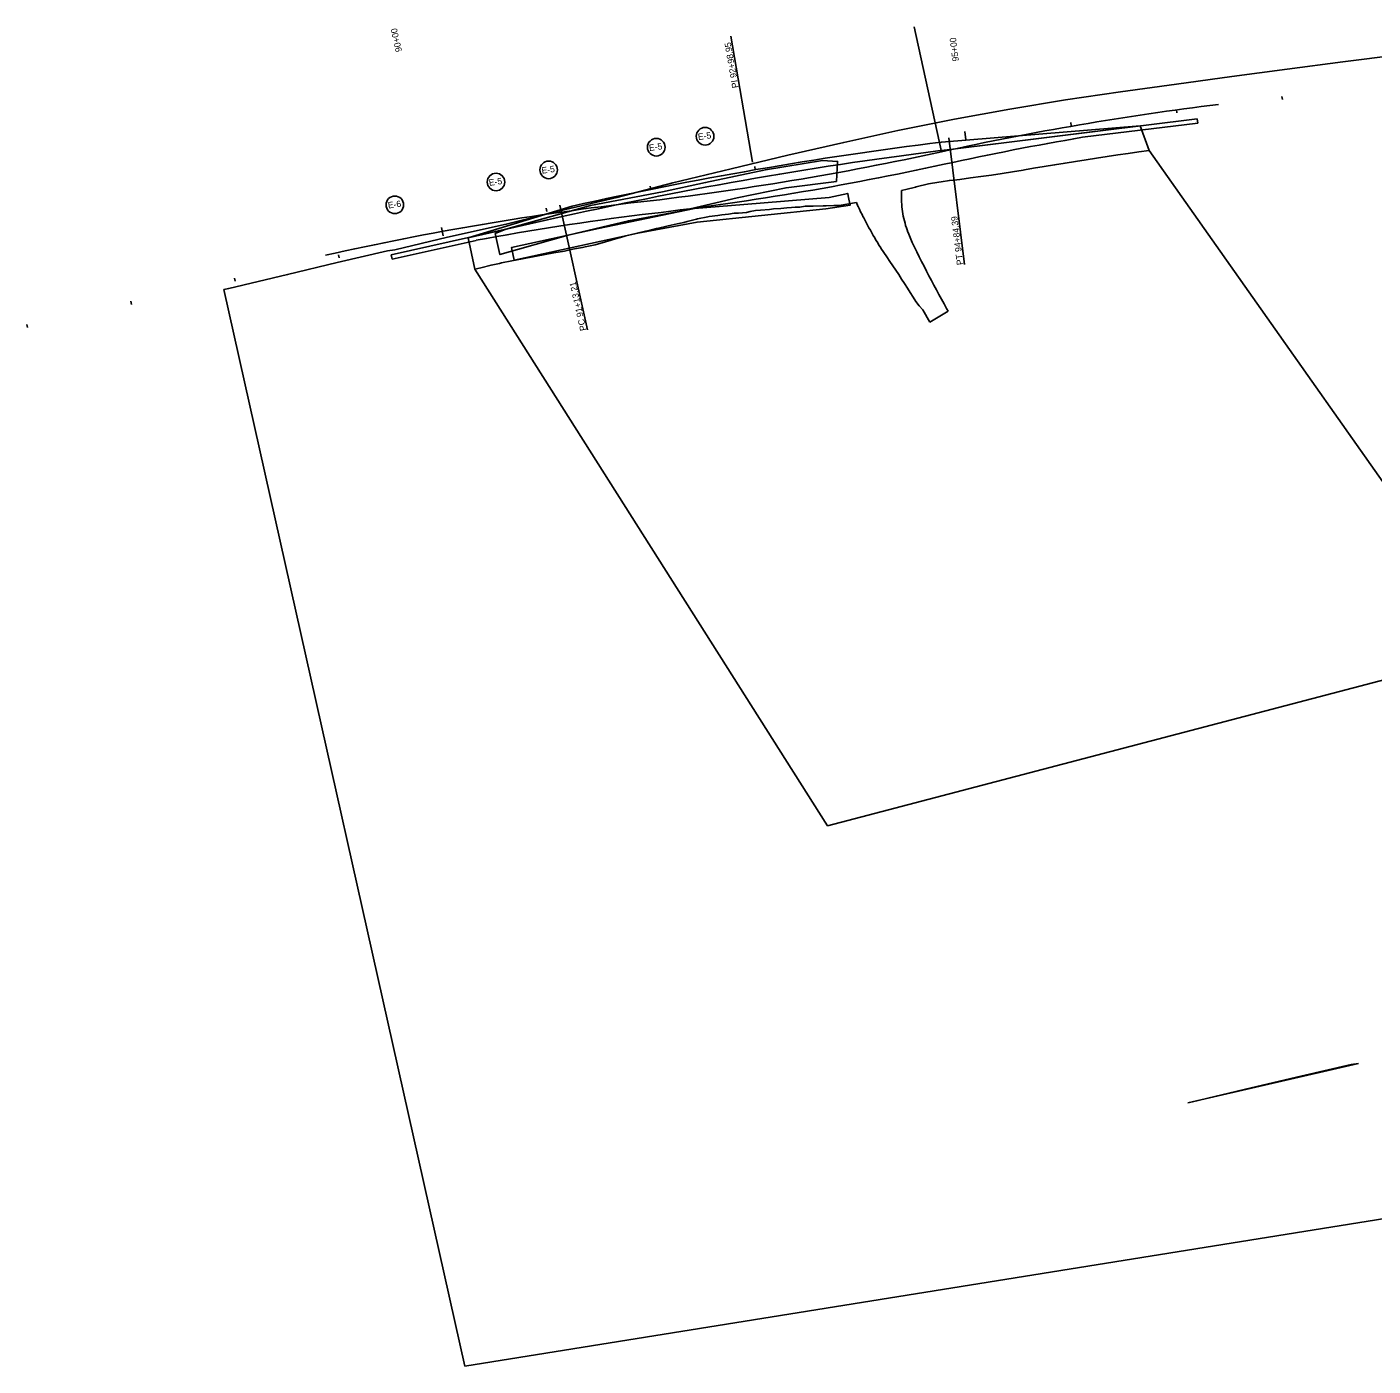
# Model space of a CAD drawing. Extents: x 1568908 to 1572777, y 730965 to 733090.
# Drawn here: x 1568908 to 1570174, y 730965 to 732223 of the extents above; entities that cross this region are included whole.
import ezdxf

# ---------------------------------------------------------------- set-up
doc = ezdxf.new("R2010")
doc.units = 0
for name, color, linetype in [('R_Erosion', 7, 'Continuous'), ('R_Horz Alg', 7, 'Continuous'), ('R_Horz Alg Annot', 7, 'Continuous'), ('R_No Plot', 7, 'Continuous')]:
    doc.layers.add(name, color=color, linetype=linetype)

msp = doc.modelspace()

# ---------------------------------------------------------------- linework, layer by layer
at = {"layer": 'R_Erosion'}
for centre in [(1569545.7, 732120.4), (1569499.8, 732110.1), (1569349.2, 732077.4), (1569398.7, 732088.8), (1569254.1, 732056)]:
    msp.add_circle(centre, 8.26, dxfattribs=at)
at = {"layer": 'R_Horz Alg'}
for centre, start, end in [((1570380, 729307.2), 97.05, 102.3359), ((1569155.9, 734904.5), 276.6023, 282.3359), ((1569814.7, 729213), 96.6023, 102.6177)]:
    msp.add_arc(centre, 2864.8, start, end, dxfattribs=at)
at = {"layer": 'R_Horz Alg Annot'}
for points in [[(1569590.4, 732096.2), (1569569.9, 732214.4)], [(1569767.9, 732105.9), (1569742.3, 732223.1)], [(1570088.3, 732154.8), (1570087.9, 732157.7)], [(1569989, 732142.5), (1569988.7, 732145.5)], [(1569789.7, 732124.9), (1569790.7, 732117)], [(1569889.8, 732130.2), (1569889.4, 732133.2)], [(1569774.7, 732119), (1569789.4, 731999.9)], [(1569592.8, 732089), (1569592.3, 732092)], [(1569494.6, 732070.7), (1569494, 732073.6)], [(1569396.9, 732049.8), (1569396.2, 732052.8)], [(1569409.1, 732055.6), (1569435.3, 731938.5)], [(1569297.8, 732034.8), (1569299.5, 732027)], [(1569201.7, 732006.1), (1569201, 732009.1)], [(1569104.1, 731984.3), (1569103.5, 731987.2)], [(1569006.5, 731962.4), (1569005.9, 731965.4)], [(1568908.9, 731940.6), (1568908.3, 731943.5)]]:
    msp.add_lwpolyline(points, dxfattribs=at)
at = {"layer": 'R_No Plot'}
for p, q in [((1570008.2, 732136.8), (1569776, 732108.1)), ((1570008.7, 732132.8), (1570008.2, 732136.8)), ((1569954.7, 732130.2), (1569767.8, 732114.9)), ((1569954.7, 732130.2), (1569776, 732108.1)), ((1569900.4, 732119.4), (1570008.7, 732132.8)), ((1569963.2, 732107), (1569954.7, 732130.2)), ((1569420.8, 732054.8), (1569323.1, 732025.1)), ((1569411.5, 732044.9), (1569250.7, 732008.9)), ((1569411.5, 732044.9), (1569323.1, 732025.1)), ((1569486.7, 732046.8), (1569486.7, 732046.8)), ((1569251.6, 732005), (1569330.4, 732022.6)), ((1569323.1, 732025.1), (1569329.4, 731995.6)), ((1569247.2, 732012.7), (1569247.1, 732012.7)), ((1569247.2, 732012.7), (1569247.1, 732012.7)), ((1569247.2, 732012.7), (1569247.1, 732012.7)), ((1569247.2, 732012.7), (1569247.1, 732012.7)), ((1569254.2, 732013.6), (1569247.2, 732012.7)), ((1569254.2, 732013.6), (1569247.2, 732012.7)), ((1569254.2, 732013.6), (1569247.2, 732012.7)), ((1569254.2, 732013.6), (1569247.2, 732012.7)), ((1569250.7, 732008.9), (1569251.6, 732005)), ((1569093.5, 731976.4), (1569320, 730964.9)), ((1569093.5, 731976.4), (1569320, 730964.9)), ((1569093.5, 731976.4), (1569320, 730964.9)), ((1569093.5, 731976.4), (1569320, 730964.9)), ((1569774.2, 731956), (1569772.7, 731958.6)), ((1569750.3, 731957.2), (1569757, 731945.8)), ((1569757, 731945.8), (1569774.2, 731956)), ((1569320, 730964.9), (1572777.4, 731520)), ((1569320, 730964.9), (1572777.4, 731520)), ((1569320, 730964.9), (1572777.4, 731520)), ((1569320, 730964.9), (1572777.4, 731520)), ((1569999.3, 731212.1), (1570159.9, 731249.3)), ((1570159.9, 731249.3), (1570152.9, 731248.4)), ((1570152.9, 731248.4), (1570152.9, 731248.4))]:
    msp.add_line(p, q, dxfattribs=at)
for points in [[(1570197.5, 732196.8), (1570145.1, 732190.3), (1570092.9, 732183.6), (1570040.7, 732176.5), (1569988.9, 732169.3), (1569936.2, 732162.2), (1569884.5, 732154.7), (1569832.2, 732146), (1569780.2, 732136.6), (1569726.9, 732125.8), (1569676, 732114.6), (1569623.4, 732102.5), (1569570.3, 732089.8), (1569515.3, 732076.5), (1569462.6, 732063), (1569409.2, 732050.3), (1569358.8, 732037.8), (1569303.6, 732025.6), (1569254.2, 732013.6)], [(1570197.5, 732196.8), (1570145.1, 732190.3), (1570092.9, 732183.6), (1570040.7, 732176.5), (1569988.9, 732169.3), (1569936.2, 732162.2), (1569884.5, 732154.7), (1569832.2, 732146), (1569780.2, 732136.6), (1569726.9, 732125.8), (1569676, 732114.6), (1569623.4, 732102.5), (1569570.3, 732089.8), (1569515.3, 732076.5), (1569462.6, 732063), (1569409.2, 732050.3), (1569358.8, 732037.8), (1569303.6, 732025.6), (1569254.2, 732013.6)], [(1570197.5, 732196.8), (1570145.1, 732190.3), (1570092.9, 732183.6), (1570040.7, 732176.5), (1569988.9, 732169.3), (1569936.2, 732162.2), (1569884.5, 732154.7), (1569832.2, 732146), (1569780.2, 732136.6), (1569726.9, 732125.8), (1569676, 732114.6), (1569623.4, 732102.5), (1569570.3, 732089.8), (1569515.3, 732076.5), (1569462.6, 732063), (1569409.2, 732050.3), (1569358.8, 732037.8), (1569303.6, 732025.6), (1569254.2, 732013.6)], [(1570197.5, 732196.8), (1570145.1, 732190.3), (1570092.9, 732183.6), (1570040.7, 732176.5), (1569988.9, 732169.3), (1569936.2, 732162.2), (1569884.5, 732154.7), (1569832.2, 732146), (1569780.2, 732136.6), (1569726.9, 732125.8), (1569676, 732114.6), (1569623.4, 732102.5), (1569570.3, 732089.8), (1569515.3, 732076.5), (1569462.6, 732063), (1569409.2, 732050.3), (1569358.8, 732037.8), (1569303.6, 732025.6), (1569254.2, 732013.6)], [(1569323.1, 732025.1), (1569329.4, 731995.6), (1569660.8, 731472.6), (1570293.5, 731638.6), (1569963.2, 732107), (1569954.7, 732130.2)], [(1569755.6, 732075.6), (1569765.5, 732077.3), (1569767.5, 732077.6), (1569775.3, 732078.9), (1569779.6, 732079.3), (1569785.2, 732079.9), (1569795.1, 732081.3), (1569805, 732082.6), (1569814.9, 732083.9), (1569824.8, 732085.5), (1569834.7, 732087), (1569844.5, 732088.6), (1569846, 732088.9), (1569854.4, 732090.3), (1569864.3, 732091.9), (1569874.2, 732093.5), (1569884, 732095.2), (1569893.9, 732096.8), (1569903.8, 732098.4), (1569913.7, 732099.9), (1569923.6, 732101.4), (1569933.5, 732102.9), (1569943.4, 732104.3), (1569953.3, 732105.7), (1569963.2, 732107)], [(1569730.2, 732069.3), (1569731.5, 732069.7), (1569734.5, 732070.4), (1569743.4, 732072.7), (1569744.1, 732072.8), (1569755.6, 732075.6)], [(1569772.7, 731958.6), (1569770.3, 731962.9), (1569767.9, 731967.3), (1569765.4, 731971.7), (1569763.1, 731976.1), (1569760.7, 731980.5), (1569758.4, 731984.9), (1569756, 731989.4), (1569753.7, 731993.8), (1569751.5, 731998.3), (1569749.2, 732002.7), (1569746.9, 732007.2), (1569744.7, 732011.7), (1569742.4, 732016.1), (1569740.2, 732020.7), (1569738.4, 732025.4), (1569736.5, 732030), (1569736.4, 732030.3), (1569735.6, 732032.4), (1569734.9, 732034.4), (1569734.9, 732034.5), (1569734.2, 732036.7), (1569733.6, 732038.7), (1569733.6, 732038.8), (1569733, 732041), (1569732.5, 732043.1), (1569732.5, 732043.2), (1569732, 732045.4), (1569731.6, 732047.6), (1569731.6, 732047.6), (1569731.3, 732049.8), (1569731, 732052), (1569731, 732052), (1569730.7, 732054.2), (1569730.5, 732056.4), (1569730.5, 732056.5), (1569730.4, 732058.6), (1569730.3, 732060.8), (1569730.3, 732061), (1569730.2, 732063), (1569730.3, 732065.2), (1569730.3, 732065.4), (1569730.2, 732067.4), (1569730.2, 732069.3)], [(1569329.4, 731995.6), (1569335, 731996.8), (1569344.6, 731999.3), (1569352.6, 732001), (1569354.4, 732001.4), (1569364.2, 732003.5), (1569374, 732005.3), (1569383.9, 732007.1), (1569393.7, 732008.9), (1569403.6, 732010.8), (1569413.4, 732012.5), (1569418.5, 732013.6), (1569423.1, 732014.7), (1569430.5, 732016), (1569432.9, 732016.4), (1569442.5, 732018.4), (1569442.5, 732018.5), (1569452.1, 732021.2), (1569454.3, 732021.9), (1569461.6, 732024.1), (1569466.1, 732025.2), (1569471.1, 732026.7), (1569477.9, 732028.5), (1569480.7, 732029.1), (1569489.8, 732031.2), (1569490.4, 732031.3), (1569490.6, 732031.3), (1569500, 732033.6), (1569501.8, 732034), (1569509.6, 732035.8), (1569513.7, 732036.8), (1569519.3, 732038.1), (1569525.6, 732039.5), (1569528.9, 732040.4), (1569537.5, 732042.5), (1569538.5, 732042.8), (1569548.3, 732044.7), (1569549.5, 732044.9), (1569557.6, 732046.1), (1569561.5, 732046.6), (1569567.6, 732047.2), (1569573.1, 732048), (1569577.2, 732048.2), (1569584.6, 732048.8), (1569588, 732049.8), (1569593.1, 732050.6), (1569597.8, 732050.9), (1569606.2, 732051.6), (1569610, 732052.2), (1569616.8, 732052.4), (1569622.4, 732053.1), (1569626.9, 732053.4), (1569630.4, 732053.7), (1569634.8, 732053.8), (1569639.8, 732054.6), (1569646.9, 732054.6), (1569647.2, 732054.6), (1569656.8, 732055), (1569659.5, 732055.1), (1569666.8, 732055.3), (1569671.8, 732055.4), (1569688.1, 732058.1)], [(1569688.1, 732058.1), (1569689.4, 732054.7), (1569689.5, 732054.5), (1569690.7, 732051.9), (1569691.9, 732049.5), (1569691.9, 732049.4), (1569693.2, 732046.8), (1569694.4, 732044.4), (1569694.5, 732044.3), (1569695.8, 732041.8), (1569697, 732039.4), (1569697.1, 732039.4), (1569698.4, 732036.9), (1569699.7, 732034.5), (1569699.7, 732034.5), (1569701.1, 732032.1), (1569702.4, 732029.7), (1569702.5, 732029.6), (1569703.8, 732027.3), (1569705.2, 732024.9), (1569705.2, 732024.8), (1569706.6, 732022.6), (1569708, 732020.2), (1569708.1, 732020), (1569709.4, 732017.9), (1569710.8, 732015.6), (1569710.9, 732015.4), (1569713.6, 732011.1), (1569716.4, 732007), (1569719.2, 732002.8), (1569722.1, 731998.7), (1569724.9, 731994.5), (1569727.7, 731990.4), (1569730.4, 731986.2), (1569733.1, 731982), (1569735.9, 731977.8), (1569738.6, 731973.6), (1569741.2, 731969.3), (1569743.8, 731965.1), (1569746.8, 731961), (1569750.3, 731957.2)], [(1569247.1, 732012.7), (1569199.9, 732001.7), (1569153.3, 731990.5), (1569098, 731977.5), (1569093.5, 731976.4)], [(1569247.1, 732012.7), (1569199.9, 732001.7), (1569153.3, 731990.5), (1569098, 731977.5), (1569093.5, 731976.4)], [(1569247.1, 732012.7), (1569199.9, 732001.7), (1569153.3, 731990.5), (1569098, 731977.5), (1569093.5, 731976.4)], [(1569247.1, 732012.7), (1569199.9, 732001.7), (1569153.3, 731990.5), (1569098, 731977.5), (1569093.5, 731976.4)], [(1570152.9, 731248.4), (1570105.7, 731237.4), (1570059.1, 731226.3), (1570003.8, 731213.2), (1569999.3, 731212.1)]]:
    msp.add_lwpolyline(points, dxfattribs=at)
for points in [[(1569348.3, 732028.9), (1569352.8, 732009.3), (1569416.9, 732027.4), (1569473.7, 732041), (1569520.9, 732049.6), (1569576, 732062.7), (1569621.8, 732072.1), (1569669.2, 732078), (1569670.2, 732096.8), (1569656, 732097.6), (1569602.4, 732089), (1569546.1, 732076.9), (1569505.7, 732068.3), (1569438.1, 732055.2), (1569358.4, 732033)], [(1569680.9, 732061.4), (1569680.3, 732064.4), (1569679.8, 732066.7), (1569662.2, 732063), (1569582.2, 732056.3), (1569535.7, 732052.4), (1569445.6, 732033.6), (1569363.6, 732015.8), (1569366.1, 732004.1), (1569482.6, 732029.4), (1569538.2, 732039.8), (1569659.3, 732052.2), (1569682.1, 732055.8)]]:
    msp.add_lwpolyline(points, close=True, dxfattribs=at)
for centre in [(1569545.7, 732120.4), (1569499.8, 732110.1), (1569349.2, 732077.4), (1569398.7, 732088.8), (1569254.1, 732056)]:
    msp.add_circle(centre, 8.26, dxfattribs=at)
for centre, radius, start, end in [((1570212.7, 728516.8), 3625.5, 97.05, 102.6177), ((1570380, 729307.2), 2852.8, 99.6779, 102.3359), ((1570243.5, 728328.2), 3808.7, 97.05, 102.6177), ((1570243.5, 728328.2), 3808.7, 97.05, 102.6177), ((1569155.9, 734904.5), 2876.8, 276.6023, 282.3359), ((1569844.5, 729218), 2851.4, 97.209, 100.3874)]:
    msp.add_arc(centre, radius, start, end, dxfattribs=at)

# ---------------------------------------------------------------- texts
at = {"layer": 'R_Erosion'}
for s, p in [('E-5 ', (1569539.4, 732116.8)), ('E-5 ', (1569493.4, 732106.5)), ('E-5 ', (1569392.4, 732085.2)), ('E-5 ', (1569342.9, 732073.8)), ('E-6 ', (1569248, 732052.5))]:
    msp.add_text(s, height=6, rotation=7.8929, dxfattribs=at).set_placement(p)
at = {"layer": 'R_Horz Alg Annot'}
for s, rotation, p in [('90+00', 102.6177, (1569260.9, 732200.4)), ('95+00', 97.05, (1569784.2, 732191.1)), ('PI 92+98.95', 99.8339, (1569577.2, 732166.2)), ('PT 94+84.39', 97.05, (1569788.4, 731999.8)), ('PC 91+13.21', 102.6177, (1569434.3, 731938.3))]:
    msp.add_text(s, height=6, rotation=rotation, dxfattribs=at).set_placement(p)

doc.saveas('drawing.dxf')
